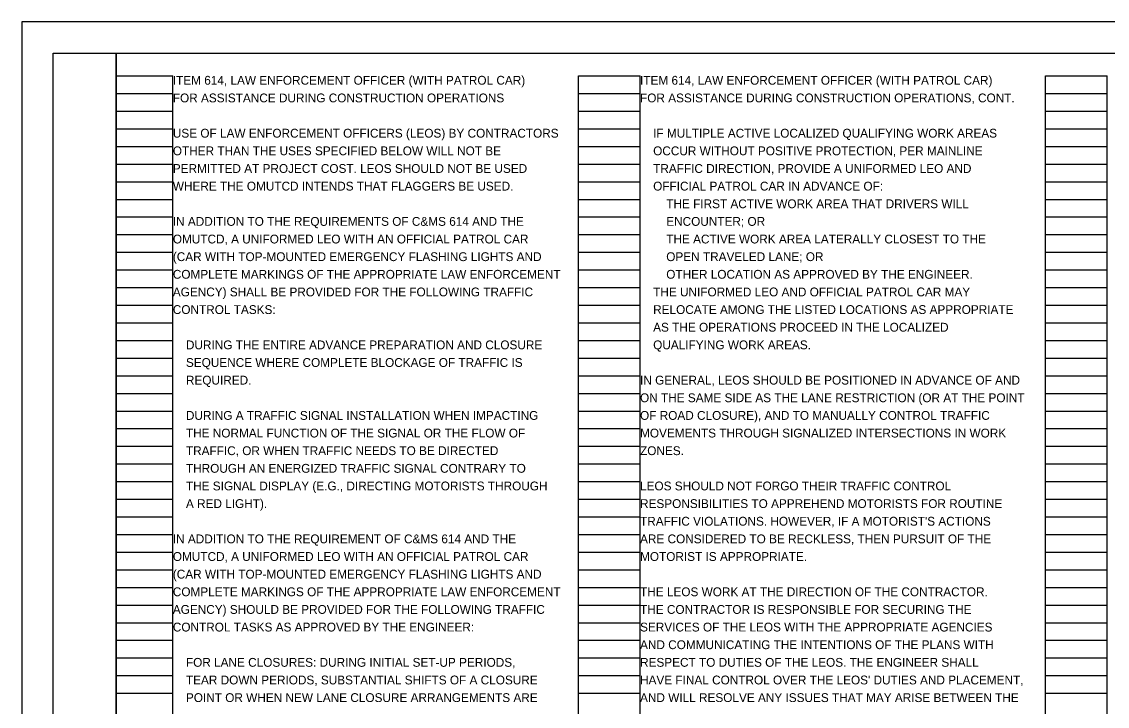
# Model space of a CAD drawing. Extents: x 0 to 34, y -13.7 to 22.
# Drawn here: x 0 to 17.24, y 11.13 to 22 of the extents above; entities that cross this region are included whole.
import ezdxf

# ---------------------------------------------------------------- set-up
doc = ezdxf.new("R2010")
doc.units = 0
for name, color, linetype in [('SH_Border', 7, 'Continuous'), ('SH_Cut_Line', 7, 'Continuous'), ('SH_Data', 7, 'Continuous'), ('SH_Text', 7, 'Continuous')]:
    doc.layers.add(name, color=color, linetype=linetype)

msp = doc.modelspace()

# ---------------------------------------------------------------- linework, layer by layer
at = {"layer": 'SH_Border'}
for points in [[(0.5, 21.5), (1.5, 21.5), (1.5, 0.5), (0.5, 0.5)], [(1.5, 21.5), (33.5, 21.5), (33.5, 0.5), (1.5, 0.5)]]:
    msp.add_lwpolyline(points, close=True, dxfattribs=at)
at = {"layer": 'SH_Cut_Line'}
msp.add_lwpolyline([(0, 0), (34, 0), (34, 22), (0, 22)], close=True, dxfattribs=at)
at = {"layer": 'SH_Data'}
for p, q in [((1.5, 0.98), (1.5, 21.14)), ((1.5, 21.14), (2.4, 21.14)), ((2.4, 0.98), (2.4, 21.14)), ((8.84, 0.98), (8.84, 21.14)), ((8.84, 21.14), (9.82, 21.14)), ((9.82, 0.98), (9.82, 21.14)), ((16.26, 0.98), (16.26, 21.14)), ((16.26, 21.14), (17.24, 21.14)), ((17.24, 0.98), (17.24, 21.14)), ((1.5, 20.86), (2.4, 20.86)), ((8.84, 20.86), (9.82, 20.86)), ((16.26, 20.86), (17.24, 20.86)), ((1.5, 20.58), (2.4, 20.58)), ((8.84, 20.58), (9.82, 20.58)), ((16.26, 20.58), (17.24, 20.58)), ((1.5, 20.3), (2.4, 20.3)), ((8.84, 20.3), (9.82, 20.3)), ((16.26, 20.3), (17.24, 20.3)), ((1.5, 20.02), (2.4, 20.02)), ((8.84, 20.02), (9.82, 20.02)), ((16.26, 20.02), (17.24, 20.02)), ((1.5, 19.74), (2.4, 19.74)), ((8.84, 19.74), (9.82, 19.74)), ((16.26, 19.74), (17.24, 19.74)), ((1.5, 19.46), (2.4, 19.46)), ((8.84, 19.46), (9.82, 19.46)), ((16.26, 19.46), (17.24, 19.46)), ((1.5, 19.18), (2.4, 19.18)), ((8.84, 19.18), (9.82, 19.18)), ((16.26, 19.18), (17.24, 19.18)), ((1.5, 18.9), (2.4, 18.9)), ((8.84, 18.9), (9.82, 18.9)), ((16.26, 18.9), (17.24, 18.9)), ((1.5, 18.62), (2.4, 18.62)), ((8.84, 18.62), (9.82, 18.62)), ((16.26, 18.62), (17.24, 18.62)), ((1.5, 18.34), (2.4, 18.34)), ((8.84, 18.34), (9.82, 18.34)), ((16.26, 18.34), (17.24, 18.34)), ((1.5, 18.06), (2.4, 18.06)), ((8.84, 18.06), (9.82, 18.06)), ((16.26, 18.06), (17.24, 18.06)), ((1.5, 17.78), (2.4, 17.78)), ((8.84, 17.78), (9.82, 17.78)), ((16.26, 17.78), (17.24, 17.78)), ((1.5, 17.5), (2.4, 17.5)), ((8.84, 17.5), (9.82, 17.5)), ((16.26, 17.5), (17.24, 17.5)), ((1.5, 17.22), (2.4, 17.22)), ((8.84, 17.22), (9.82, 17.22)), ((16.26, 17.22), (17.24, 17.22)), ((1.5, 16.94), (2.4, 16.94)), ((8.84, 16.94), (9.82, 16.94)), ((16.26, 16.94), (17.24, 16.94)), ((1.5, 16.66), (2.4, 16.66)), ((8.84, 16.66), (9.82, 16.66)), ((16.26, 16.66), (17.24, 16.66)), ((1.5, 16.38), (2.4, 16.38)), ((8.84, 16.38), (9.82, 16.38)), ((16.26, 16.38), (17.24, 16.38)), ((1.5, 16.1), (2.4, 16.1)), ((8.84, 16.1), (9.82, 16.1)), ((16.26, 16.1), (17.24, 16.1)), ((1.5, 15.82), (2.4, 15.82)), ((8.84, 15.82), (9.82, 15.82)), ((16.26, 15.82), (17.24, 15.82)), ((1.5, 15.54), (2.4, 15.54)), ((8.84, 15.54), (9.82, 15.54)), ((16.26, 15.54), (17.24, 15.54)), ((1.5, 15.26), (2.4, 15.26)), ((8.84, 15.26), (9.82, 15.26)), ((16.26, 15.26), (17.24, 15.26)), ((1.5, 14.98), (2.4, 14.98)), ((8.84, 14.98), (9.82, 14.98)), ((16.26, 14.98), (17.24, 14.98)), ((1.5, 14.7), (2.4, 14.7)), ((8.84, 14.7), (9.82, 14.7)), ((16.26, 14.7), (17.24, 14.7)), ((1.5, 14.42), (2.4, 14.42)), ((8.84, 14.42), (9.82, 14.42)), ((16.26, 14.42), (17.24, 14.42)), ((1.5, 14.14), (2.4, 14.14)), ((8.84, 14.14), (9.82, 14.14)), ((16.26, 14.14), (17.24, 14.14)), ((1.5, 13.86), (2.4, 13.86)), ((8.84, 13.86), (9.82, 13.86)), ((16.26, 13.86), (17.24, 13.86)), ((1.5, 13.58), (2.4, 13.58)), ((8.84, 13.58), (9.82, 13.58)), ((16.26, 13.58), (17.24, 13.58)), ((1.5, 13.3), (2.4, 13.3)), ((8.84, 13.3), (9.82, 13.3)), ((16.26, 13.3), (17.24, 13.3)), ((1.5, 13.02), (2.4, 13.02)), ((8.84, 13.02), (9.82, 13.02)), ((16.26, 13.02), (17.24, 13.02)), ((1.5, 12.74), (2.4, 12.74)), ((8.84, 12.74), (9.82, 12.74)), ((16.26, 12.74), (17.24, 12.74)), ((1.5, 12.46), (2.4, 12.46)), ((8.84, 12.46), (9.82, 12.46)), ((16.26, 12.46), (17.24, 12.46)), ((1.5, 12.18), (2.4, 12.18)), ((8.84, 12.18), (9.82, 12.18)), ((16.26, 12.18), (17.24, 12.18)), ((1.5, 11.9), (2.4, 11.9)), ((8.84, 11.9), (9.82, 11.9)), ((16.26, 11.9), (17.24, 11.9)), ((1.5, 11.62), (2.4, 11.62)), ((8.84, 11.62), (9.82, 11.62)), ((16.26, 11.62), (17.24, 11.62)), ((1.5, 11.34), (2.4, 11.34)), ((8.84, 11.34), (9.82, 11.34)), ((16.26, 11.34), (17.24, 11.34))]:
    msp.add_line(p, q, dxfattribs=at)

# ---------------------------------------------------------------- texts
at = {"layer": 'SH_Text'}
for s, p in [('ITEM 614, LAW ENFORCEMENT OFFICER (WITH PATROL CAR)', (2.4, 21)), ('ITEM 614, LAW ENFORCEMENT OFFICER (WITH PATROL CAR)', (9.82, 21)), ('FOR ASSISTANCE DURING CONSTRUCTION OPERATIONS', (2.4, 20.72)), ('FOR ASSISTANCE DURING CONSTRUCTION OPERATIONS, CONT.', (9.82, 20.72)), ('USE OF LAW ENFORCEMENT OFFICERS (LEOS) BY CONTRACTORS', (2.4, 20.16)), ('    IF MULTIPLE ACTIVE LOCALIZED QUALIFYING WORK AREAS', (9.82, 20.16)), ('OTHER THAN THE USES SPECIFIED BELOW WILL NOT BE', (2.4, 19.88)), ('    OCCUR WITHOUT POSITIVE PROTECTION, PER MAINLINE', (9.82, 19.88)), ('PERMITTED AT PROJECT COST. LEOS SHOULD NOT BE USED', (2.4, 19.6)), ('    TRAFFIC DIRECTION, PROVIDE A UNIFORMED LEO AND', (9.82, 19.6)), ('WHERE THE OMUTCD INTENDS THAT FLAGGERS BE USED.', (2.4, 19.32)), ('    OFFICIAL PATROL CAR IN ADVANCE OF:', (9.82, 19.32)), ('        THE FIRST ACTIVE WORK AREA THAT DRIVERS WILL', (9.82, 19.04)), ('IN ADDITION TO THE REQUIREMENTS OF C&MS 614 AND THE', (2.4, 18.76)), ('        ENCOUNTER; OR', (9.82, 18.76)), ('OMUTCD, A UNIFORMED LEO WITH AN OFFICIAL PATROL CAR', (2.4, 18.48)), ('        THE ACTIVE WORK AREA LATERALLY CLOSEST TO THE', (9.82, 18.48)), ('(CAR WITH TOP-MOUNTED EMERGENCY FLASHING LIGHTS AND', (2.4, 18.2)), ('        OPEN TRAVELED LANE; OR', (9.82, 18.2)), ('COMPLETE MARKINGS OF THE APPROPRIATE LAW ENFORCEMENT', (2.4, 17.92)), ('        OTHER LOCATION AS APPROVED BY THE ENGINEER.', (9.82, 17.92)), ('AGENCY) SHALL BE PROVIDED FOR THE FOLLOWING TRAFFIC', (2.4, 17.64)), ('    THE UNIFORMED LEO AND OFFICIAL PATROL CAR MAY', (9.82, 17.64)), ('CONTROL TASKS:', (2.4, 17.36)), ('    RELOCATE AMONG THE LISTED LOCATIONS AS APPROPRIATE', (9.82, 17.36)), ('    AS THE OPERATIONS PROCEED IN THE LOCALIZED', (9.82, 17.08)), ('    DURING THE ENTIRE ADVANCE PREPARATION AND CLOSURE', (2.4, 16.8)), ('    QUALIFYING WORK AREAS.', (9.82, 16.8)), ('    SEQUENCE WHERE COMPLETE BLOCKAGE OF TRAFFIC IS', (2.4, 16.52)), ('    REQUIRED.', (2.4, 16.24)), ('IN GENERAL, LEOS SHOULD BE POSITIONED IN ADVANCE OF AND', (9.82, 16.24)), ('ON THE SAME SIDE AS THE LANE RESTRICTION (OR AT THE POINT', (9.82, 15.96)), ('    DURING A TRAFFIC SIGNAL INSTALLATION WHEN IMPACTING', (2.4, 15.68)), ('OF ROAD CLOSURE), AND TO MANUALLY CONTROL TRAFFIC', (9.82, 15.68)), ('    THE NORMAL FUNCTION OF THE SIGNAL OR THE FLOW OF', (2.4, 15.4)), ('MOVEMENTS THROUGH SIGNALIZED INTERSECTIONS IN WORK', (9.82, 15.4)), ('    TRAFFIC, OR WHEN TRAFFIC NEEDS TO BE DIRECTED', (2.4, 15.12)), ('ZONES.', (9.82, 15.12)), ('    THROUGH AN ENERGIZED TRAFFIC SIGNAL CONTRARY TO', (2.4, 14.84)), ('    THE SIGNAL DISPLAY (E.G., DIRECTING MOTORISTS THROUGH', (2.4, 14.56)), ('LEOS SHOULD NOT FORGO THEIR TRAFFIC CONTROL', (9.82, 14.56)), ('    A RED LIGHT).', (2.4, 14.28)), ('RESPONSIBILITIES TO APPREHEND MOTORISTS FOR ROUTINE', (9.82, 14.28)), ("TRAFFIC VIOLATIONS. HOWEVER, IF A MOTORIST'S ACTIONS", (9.82, 14)), ('IN ADDITION TO THE REQUIREMENT OF C&MS 614 AND THE', (2.4, 13.72)), ('ARE CONSIDERED TO BE RECKLESS, THEN PURSUIT OF THE', (9.82, 13.72)), ('OMUTCD, A UNIFORMED LEO WITH AN OFFICIAL PATROL CAR', (2.4, 13.44)), ('MOTORIST IS APPROPRIATE.', (9.82, 13.44)), ('(CAR WITH TOP-MOUNTED EMERGENCY FLASHING LIGHTS AND', (2.4, 13.16)), ('COMPLETE MARKINGS OF THE APPROPRIATE LAW ENFORCEMENT', (2.4, 12.88)), ('THE LEOS WORK AT THE DIRECTION OF THE CONTRACTOR.', (9.82, 12.88)), ('AGENCY) SHOULD BE PROVIDED FOR THE FOLLOWING TRAFFIC', (2.4, 12.6)), ('THE CONTRACTOR IS RESPONSIBLE FOR SECURING THE', (9.82, 12.6)), ('CONTROL TASKS AS APPROVED BY THE ENGINEER:', (2.4, 12.32)), ('SERVICES OF THE LEOS WITH THE APPROPRIATE AGENCIES', (9.82, 12.32)), ('AND COMMUNICATING THE INTENTIONS OF THE PLANS WITH', (9.82, 12.04)), ('    FOR LANE CLOSURES: DURING INITIAL SET-UP PERIODS,', (2.4, 11.76)), ('RESPECT TO DUTIES OF THE LEOS. THE ENGINEER SHALL', (9.82, 11.76)), ('    TEAR DOWN PERIODS, SUBSTANTIAL SHIFTS OF A CLOSURE', (2.4, 11.48)), ("HAVE FINAL CONTROL OVER THE LEOS' DUTIES AND PLACEMENT,", (9.82, 11.48)), ('    POINT OR WHEN NEW LANE CLOSURE ARRANGEMENTS ARE', (2.4, 11.2)), ('AND WILL RESOLVE ANY ISSUES THAT MAY ARISE BETWEEN THE', (9.82, 11.2))]:
    msp.add_text(s, height=0.14, dxfattribs=at).set_placement(p)

doc.saveas('drawing.dxf')
